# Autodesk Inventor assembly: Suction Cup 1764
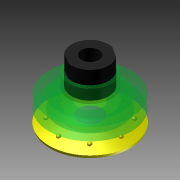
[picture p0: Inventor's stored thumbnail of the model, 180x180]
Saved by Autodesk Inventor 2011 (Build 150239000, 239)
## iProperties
Created: 2010-02
Part Number: Suction Cup 1764
Document SubType Name: Assembly
Designer: clee1
Author: clee1
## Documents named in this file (4)
- R:\CAD Archives\Pnewmatics\Suction Cups\Suction Cup 1764\Suction Cup 1764.iam
- R:\CAD Archives\Pnewmatics\Suction Cups\Suction Cup 1764\Suctin Cup Part 1 1764.ipt
- R:\CAD Archives\Pnewmatics\Suction Cups\Suction Cup 1764\Suction Cup Part 2 1764.ipt
- R:\CAD Archives\Pnewmatics\Suction Cups\Suction Cup 1764\Suction Cup Part 3 1764.ipt
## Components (3 placed, 3 different names)
1. Suctin Cup Part 1 1764:1 — Insert:1, Insert:2
2. Suction Cup Part 2 1764:1 — Insert:1
3. Suction Cup Part 3 1764:1 — Insert:2
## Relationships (2: Insert 2)
- Insert:1: Suctin Cup Part 1 1764:1 ↔ Suction Cup Part 2 1764:1
- Insert:2: Suctin Cup Part 1 1764:1 ↔ Suction Cup Part 3 1764:1
